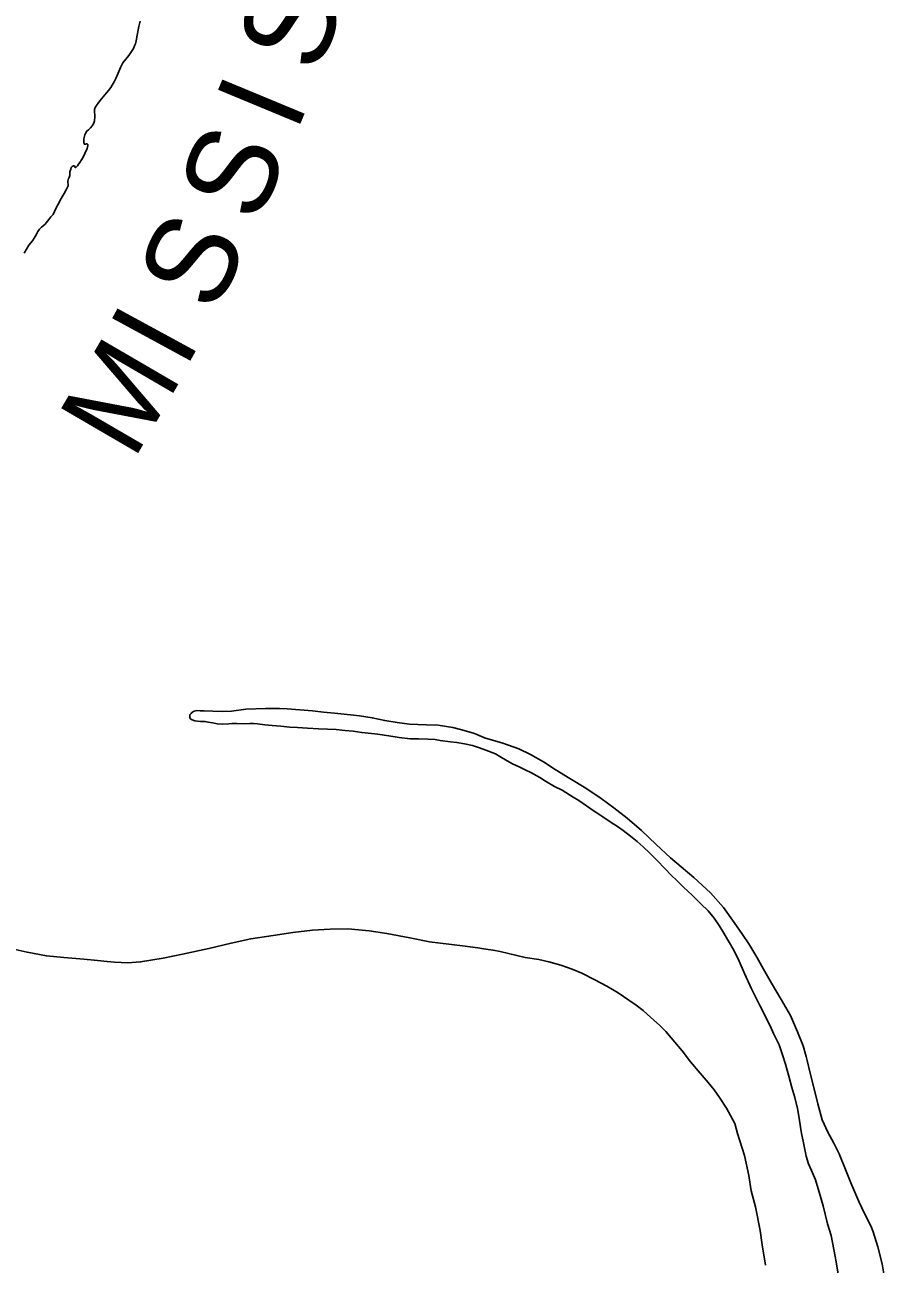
# Model space of a CAD drawing. Extents: x -939622 to -934222, y 1383701 to 1385301.
# Drawn here: x -935796.77 to -935778.4, y 1383856.62 to 1383883.08 of the extents above; entities that cross this region are included whole.
import ezdxf

# ---------------------------------------------------------------- set-up
doc = ezdxf.new("R2010")
doc.units = 0
doc.layers.add('Level 3', color=7, linetype='Continuous')
doc.layers.add('Level 9', color=7, linetype='Continuous')

msp = doc.modelspace()

# ---------------------------------------------------------------- linework, layer by layer
at = {"layer": 'Level 3'}
for points in [[(-935797.101, 1383863.368), (-935796.72, 1383863.277), (-935796.308, 1383863.201), (-935795.935, 1383863.164), (-935795.511, 1383863.128), (-935795.217, 1383863.104), (-935795.013, 1383863.083), (-935794.856, 1383863.066), (-935794.568, 1383863.053), (-935794.296, 1383863.07), (-935793.816, 1383863.154), (-935793.402, 1383863.238), (-935792.839, 1383863.357), (-935792.366, 1383863.473), (-935791.943, 1383863.567), (-935791.465, 1383863.638), (-935791.045, 1383863.698), (-935790.627, 1383863.75), (-935790.25, 1383863.773), (-935789.872, 1383863.775), (-935789.415, 1383863.734), (-935789.039, 1383863.675), (-935788.545, 1383863.584), (-935788.129, 1383863.503), (-935787.422, 1383863.416), (-935787.097, 1383863.374), (-935786.925, 1383863.346), (-935786.772, 1383863.32), (-935786.621, 1383863.297), (-935786.084, 1383863.169), (-935785.792, 1383863.12), (-935785.584, 1383863.075), (-935785.327, 1383863.004), (-935785.082, 1383862.918), (-935784.875, 1383862.831), (-935784.598, 1383862.688), (-935784.34, 1383862.554), (-935784.102, 1383862.411), (-935783.875, 1383862.255)], [(-935783.875, 1383862.255), (-935783.716, 1383862.148), (-935783.569, 1383862.035), (-935783.4, 1383861.883), (-935783.221, 1383861.723), (-935783.086, 1383861.588), (-935782.968, 1383861.453), (-935782.735, 1383861.174), (-935782.557, 1383860.941), (-935782.349, 1383860.698), (-935782.181, 1383860.495), (-935782.054, 1383860.339), (-935781.935, 1383860.177), (-935781.788, 1383859.952), (-935781.61, 1383859.623), (-935781.55, 1383859.408), (-935781.407, 1383858.94), (-935781.311, 1383858.509), (-935781.259, 1383858.186), (-935781.168, 1383857.842), (-935781.07, 1383857.339), (-935781.025, 1383857.03), (-935780.955, 1383856.599)]]:
    msp.add_lwpolyline(points, dxfattribs=at)
at = {"layer": 'Level 9'}
for points in [[(-935794.308, 1383883.159), (-935794.335, 1383883.044), (-935794.369, 1383882.863), (-935794.392, 1383882.741), (-935794.408, 1383882.675), (-935794.428, 1383882.632), (-935794.45, 1383882.577), (-935794.508, 1383882.494), (-935794.548, 1383882.43), (-935794.672, 1383882.267), (-935794.726, 1383882.172), (-935794.776, 1383882.053), (-935794.827, 1383881.937), (-935794.852, 1383881.876), (-935794.932, 1383881.741), (-935794.981, 1383881.677), (-935795.022, 1383881.63), (-935795.129, 1383881.504), (-935795.189, 1383881.427), (-935795.236, 1383881.362), (-935795.264, 1383881.313), (-935795.278, 1383881.271), (-935795.283, 1383881.228), (-935795.279, 1383881.204), (-935795.275, 1383881.171), (-935795.273, 1383881.12), (-935795.283, 1383881.03), (-935795.296, 1383880.981), (-935795.33, 1383880.923), (-935795.368, 1383880.883), (-935795.409, 1383880.842), (-935795.441, 1383880.814), (-935795.467, 1383880.774), (-935795.487, 1383880.735), (-935795.508, 1383880.644), (-935795.51, 1383880.601), (-935795.506, 1383880.571), (-935795.499, 1383880.548), (-935795.496, 1383880.533), (-935795.484, 1383880.53), (-935795.472, 1383880.536), (-935795.451, 1383880.543), (-935795.439, 1383880.54), (-935795.421, 1383880.523), (-935795.42, 1383880.508), (-935795.439, 1383880.438), (-935795.484, 1383880.334), (-935795.524, 1383880.258), (-935795.561, 1383880.2), (-935795.595, 1383880.144), (-935795.621, 1383880.107), (-935795.644, 1383880.071), (-935795.664, 1383880.046), (-935795.682, 1383880.033), (-935795.691, 1383880.036), (-935795.71, 1383880.069), (-935795.731, 1383880.068), (-935795.755, 1383880.058), (-935795.775, 1383880.034), (-935795.786, 1383880.003), (-935795.805, 1383879.943), (-935795.81, 1383879.912), (-935795.809, 1383879.867), (-935795.822, 1383879.819), (-935795.834, 1383879.8), (-935795.847, 1383879.746), (-935795.849, 1383879.712), (-935795.845, 1383879.673), (-935795.844, 1383879.646), (-935795.87, 1383879.585), (-935795.884, 1383879.558), (-935795.929, 1383879.481), (-935795.992, 1383879.371), (-935796.06, 1383879.24), (-935796.103, 1383879.163), (-935796.165, 1383879.035), (-935796.215, 1383878.985), (-935796.255, 1383878.927), (-935796.31, 1383878.853), (-935796.336, 1383878.822), (-935796.377, 1383878.791), (-935796.415, 1383878.763), (-935796.455, 1383878.716), (-935796.487, 1383878.67), (-935796.524, 1383878.6)], [(-935796.524, 1383878.6), (-935796.57, 1383878.526), (-935796.604, 1383878.468), (-935796.682, 1383878.376), (-935796.785, 1383878.204)], [(-935783.57, 1383865.53), (-935783.696, 1383865.641), (-935783.838, 1383865.754), (-935783.994, 1383865.876), (-935784.116, 1383865.963), (-935784.269, 1383866.061), (-935784.425, 1383866.167), (-935784.495, 1383866.21), (-935784.615, 1383866.291), (-935784.777, 1383866.407), (-935784.942, 1383866.52), (-935785.058, 1383866.588), (-935785.293, 1383866.741), (-935785.457, 1383866.821), (-935785.649, 1383866.932), (-935785.772, 1383867.01), (-935785.967, 1383867.119), (-935786.088, 1383867.173), (-935786.201, 1383867.229), (-935786.359, 1383867.303), (-935786.471, 1383867.366), (-935786.624, 1383867.461), (-935786.718, 1383867.515), (-935786.925, 1383867.594), (-935787.058, 1383867.644), (-935787.212, 1383867.691), (-935787.384, 1383867.731), (-935787.547, 1383867.756), (-935787.679, 1383867.773), (-935787.899, 1383867.803), (-935788.01, 1383867.818), (-935788.16, 1383867.826), (-935788.364, 1383867.835), (-935788.544, 1383867.838), (-935788.776, 1383867.862), (-935788.998, 1383867.9), (-935789.242, 1383867.935), (-935789.365, 1383867.947), (-935789.576, 1383867.974), (-935789.757, 1383867.996), (-935789.937, 1383868.015), (-935790.123, 1383868.033), (-935790.306, 1383868.043), (-935790.495, 1383868.046), (-935790.73, 1383868.064), (-935790.949, 1383868.078), (-935791.108, 1383868.086), (-935791.306, 1383868.104), (-935791.489, 1383868.12), (-935791.643, 1383868.136), (-935791.799, 1383868.156), (-935791.883, 1383868.162), (-935791.961, 1383868.166), (-935792.09, 1383868.159), (-935792.243, 1383868.161), (-935792.345, 1383868.164), (-935792.411, 1383868.156), (-935792.539, 1383868.149), (-935792.659, 1383868.158), (-935792.756, 1383868.176), (-935792.858, 1383868.194), (-935792.915, 1383868.202), (-935793.017, 1383868.208), (-935793.081, 1383868.215), (-935793.141, 1383868.222), (-935793.195, 1383868.242), (-935793.223, 1383868.256), (-935793.247, 1383868.282), (-935793.248, 1383868.309), (-935793.246, 1383868.345), (-935793.241, 1383868.355), (-935793.22, 1383868.379), (-935793.2, 1383868.395), (-935793.153, 1383868.423), (-935793.093, 1383868.437), (-935793.027, 1383868.436), (-935792.937, 1383868.433), (-935792.757, 1383868.423), (-935792.553, 1383868.417), (-935792.353, 1383868.429), (-935792.048, 1383868.471), (-935791.629, 1383868.483), (-935791.332, 1383868.486), (-935791.17, 1383868.478), (-935790.624, 1383868.434), (-935790.389, 1383868.408), (-935790.16, 1383868.381), (-935789.812, 1383868.349), (-935789.622, 1383868.328), (-935789.351, 1383868.284), (-935789.083, 1383868.226), (-935788.818, 1383868.183), (-935788.556, 1383868.151), (-935788.379, 1383868.138), (-935788.196, 1383868.135), (-935787.947, 1383868.124), (-935787.628, 1383868.079), (-935787.435, 1383868.027), (-935787.166, 1383867.951), (-935786.969, 1383867.866), (-935786.953, 1383867.858)], [(-935786.953, 1383867.858), (-935786.566, 1383867.743), (-935786.218, 1383867.62), (-935785.975, 1383867.504), (-935785.692, 1383867.347), (-935785.444, 1383867.179), (-935785.13, 1383866.99), (-935784.794, 1383866.78), (-935784.467, 1383866.561), (-935784.191, 1383866.361), (-935783.912, 1383866.143), (-935783.602, 1383865.881), (-935783.287, 1383865.58), (-935782.985, 1383865.297), (-935782.757, 1383865.099), (-935782.487, 1383864.875), (-935782.13, 1383864.548), (-935781.851, 1383864.234), (-935781.626, 1383863.916), (-935781.444, 1383863.659), (-935781.309, 1383863.455), (-935781.139, 1383863.171), (-935780.997, 1383862.914), (-935780.826, 1383862.615), (-935780.621, 1383862.268), (-935780.425, 1383861.931), (-935780.271, 1383861.58), (-935780.152, 1383861.283), (-935780.085, 1383861.053), (-935780.064, 1383860.966), (-935780.003, 1383860.697), (-935779.918, 1383860.365), (-935779.836, 1383860.042), (-935779.748, 1383859.699), (-935779.627, 1383859.434), (-935779.497, 1383859.2), (-935779.385, 1383858.975), (-935779.25, 1383858.642), (-935779.133, 1383858.356), (-935778.96, 1383857.955), (-935778.832, 1383857.684), (-935778.708, 1383857.438), (-935778.659, 1383857.307), (-935778.554, 1383856.991), (-935778.468, 1383856.623), (-935778.4, 1383856.24)], [(-935779.398, 1383856.358), (-935779.449, 1383856.667), (-935779.496, 1383856.933), (-935779.556, 1383857.227), (-935779.629, 1383857.477), (-935779.727, 1383857.866), (-935779.811, 1383858.153), (-935779.888, 1383858.418), (-935779.971, 1383858.617), (-935780.036, 1383858.763), (-935780.088, 1383858.924), (-935780.152, 1383859.241), (-935780.186, 1383859.406), (-935780.208, 1383859.541), (-935780.235, 1383859.733), (-935780.271, 1383859.945), (-935780.332, 1383860.178), (-935780.395, 1383860.387), (-935780.459, 1383860.629), (-935780.527, 1383860.886), (-935780.589, 1383861.089), (-935780.665, 1383861.298), (-935780.786, 1383861.544), (-935780.853, 1383861.708), (-935781.073, 1383862.141), (-935781.251, 1383862.497), (-935781.402, 1383862.827), (-935781.517, 1383863.088), (-935781.629, 1383863.32), (-935781.746, 1383863.515), (-935781.866, 1383863.719), (-935781.947, 1383863.849), (-935782.048, 1383864.003), (-935782.181, 1383864.162), (-935782.333, 1383864.314), (-935782.521, 1383864.495), (-935782.703, 1383864.67), (-935782.851, 1383864.81), (-935782.971, 1383864.924), (-935783.101, 1383865.059), (-935783.277, 1383865.241), (-935783.428, 1383865.396), (-935783.57, 1383865.53)]]:
    msp.add_lwpolyline(points, dxfattribs=at)

# ---------------------------------------------------------------- texts
for s, rotation, p in [('S', 70.4715, (-935790.496, 1383882.001)), ('I', 67.4612, (-935790.976, 1383880.75)), ('S', 66.9548, (-935791.8, 1383878.797)), ('S', 64.4715, (-935792.714, 1383876.884)), ('I', 61.4612, (-935793.345, 1383875.702)), ('M', 59.7564, (-935794.453, 1383873.757))]:
    msp.add_text(s, height=1.901, rotation=rotation, dxfattribs=at).set_placement(p)

doc.saveas('drawing.dxf')
